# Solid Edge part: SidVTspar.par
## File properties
Author: harmonj5
Template: ansi part.par
Last saved by: harmonj5
Revision: 7
Application: Solid Edge
Accuracy: 0.990
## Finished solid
Body 1: solid body, 6 faces, 12 edges, 8 vertices.
  Faces by surface: plane 6
  Edges by curve: line 12
Bounding box of the edges (mm): 6.477 x 273.050 x 3.302, from (-62.96, 0, 8.3687) to (-56.483, 273.05, 11.6707).
Planar faces by outward normal: +x 1, +y 1, +z 1, -x 1, -y 1, -z 1
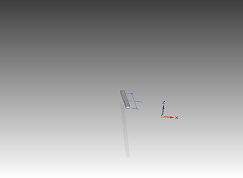
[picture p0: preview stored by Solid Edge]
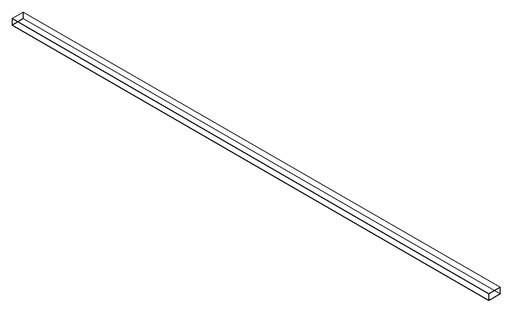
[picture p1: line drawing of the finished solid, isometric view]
